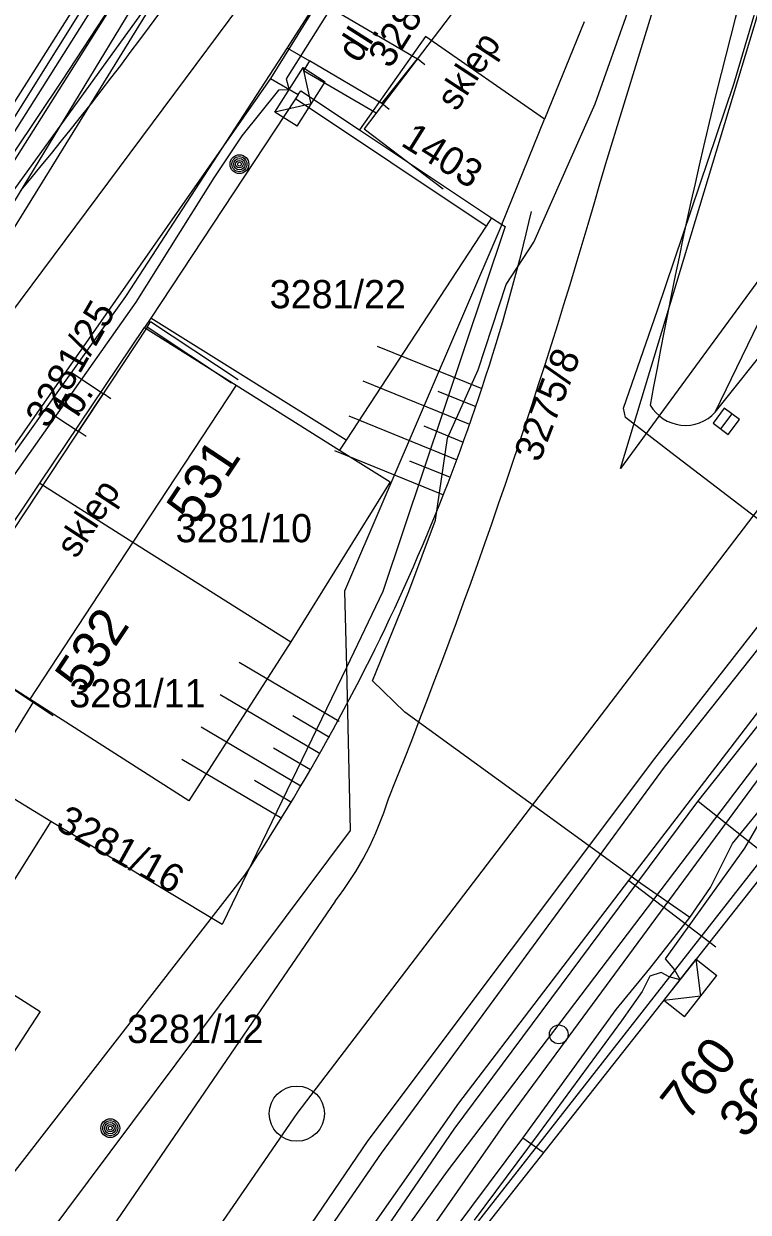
# Model space of a CAD drawing. Extents: x -601580 to 4, y -1204314 to 4.
# Drawn here: x -599644.63 to -599625.36, y -1204061.88 to -1204030.29 of the extents above; entities that cross this region are included whole.
import ezdxf

# ---------------------------------------------------------------- set-up
doc = ezdxf.new("R2010")
doc.units = 0
for name, color, linetype in [('00-EON NN', 7, 'Continuous'), ('00-INNOGY-NTL', 7, 'Continuous'), ('00-KN-HRANICE PARCEL', 7, 'Continuous'), ('00-KN-PARC. CISLA', 7, 'Continuous'), ('00-KN-VNITRNI KRESBA', 7, 'Continuous'), ('00-POLOHOPIS', 7, 'Continuous'), ('00-SITE KOM. KABEL', 7, 'Continuous'), ('00-VAK-KANAL-POTRUBI', 7, 'Continuous'), ('00-VAK-VODA-RAD IGIS', 7, 'Continuous'), ('Vrstva 25', 7, 'Continuous'), ('Vrstva 27', 7, 'Continuous'), ('Vrstva 28', 7, 'Continuous'), ('Vrstva 6', 7, 'Continuous'), ('Vrstva 9', 7, 'Continuous')]:
    doc.layers.add(name, color=color, linetype=linetype)

# ---------------------------------------------------------------- blocks, each defined once
blk = doc.blocks.new('6.01A_958')
at = {"layer": 'Vrstva 25'}
for radius in [0.25, 0.2, 0.15, 0.1, 0.05]:
    blk.add_circle((0, 0), radius, dxfattribs=at)
blk = doc.blocks.new('6.01A_960')
at = {"layer": 'Vrstva 25'}
for radius in [0.25, 0.2, 0.15, 0.1, 0.05]:
    blk.add_circle((0, 0), radius, dxfattribs=at)
blk = doc.blocks.new('6.14A_116')
at = {"layer": 'Vrstva 28'}
blk.add_circle((0, 0), 0.25, dxfattribs=at)
blk = doc.blocks.new('6.30_54')
at = {"layer": 'Vrstva 27'}
blk.add_line((-0.25, 0), (0.25, 0), dxfattribs=at)
blk.add_lwpolyline([(-0.25, -0.25), (0.25, -0.25), (0.25, 0.25), (-0.25, 0.25)], close=True, dxfattribs=at)
blk = doc.blocks.new('VCHOD_1550')
at = {"layer": 'Vrstva 6'}
blk.add_line((0, 0.251), (0, 0), dxfattribs=at)
blk = doc.blocks.new('VCHOD_1552')
at = {"layer": 'Vrstva 6'}
blk.add_line((0, 0.251), (0, 0), dxfattribs=at)
blk = doc.blocks.new('VCHOD_1554')
at = {"layer": 'Vrstva 6'}
blk.add_line((0, 0.25), (0, 0), dxfattribs=at)
blk = doc.blocks.new('VCHOD_1556')
at = {"layer": 'Vrstva 6'}
blk.add_line((0, 0.25), (0, 0), dxfattribs=at)
blk = doc.blocks.new('NN630')
at = {"layer": 'Vrstva 9'}
for points in [[(-3, -700), (-703, 0)], [(-703, -700), (-703, 0), (697, 0), (697, -700)], [(-3, -700), (697, 0)], [(-703, -700), (697, -700)]]:
    blk.add_lwpolyline(points, dxfattribs=at)

msp = doc.modelspace()

# ---------------------------------------------------------------- linework, layer by layer
at = {"layer": '00-EON NN'}
for points in [[(-599639.626, -1204025.602), (-599645.817, -1204035.392), (-599652.109, -1204039.668), (-599681.701, -1204079.546), (-599681.569, -1204080.026), (-599681.369, -1204080.316), (-599681.408, -1204080.723), (-599688.696, -1204090.4), (-599688.958, -1204090.416)], [(-599674.016, -1204068.519), (-599668.892, -1204061.614), (-599668.999, -1204061.544), (-599668.975, -1204061.303), (-599668.772, -1204061.218), (-599668.654, -1204061.293), (-599660.063, -1204049.715), (-599660.057, -1204049.47), (-599659.824, -1204049.394), (-599657.673, -1204046.495), (-599657.713, -1204046.217), (-599657.435, -1204046.173), (-599652.394, -1204039.38), (-599646.111, -1204035.109), (-599640.072, -1204025.558)], [(-599634.111, -1204026.139), (-599637.649, -1204031.756), (-599637.575, -1204032.05), (-599637.859, -1204032.056), (-599638.829, -1204033.276), (-599639.579, -1204034.386), (-599641.649, -1204037.696), (-599646.569, -1204044.656), (-599649.609, -1204049.086), (-599651.239, -1204051.216), (-599652.409, -1204052.916), (-599655.679, -1204058.396), (-599656.009, -1204058.936), (-599655.859, -1204059.306), (-599655.181, -1204060.036)], [(-599640.793, -1204072.36), (-599631.81, -1204059.488), (-599624.178, -1204049.131), (-599611.694, -1204033.201), (-599608.009, -1204028.683)], [(-599623.769, -1204049.286), (-599625.46, -1204052.206), (-599627.574, -1204055.15), (-599627.329, -1204055.44), (-599627.177, -1204055.706), (-599627.47, -1204055.627), (-599627.678, -1204055.511), (-599627.979, -1204055.606), (-599628.189, -1204056.016), (-599628.739, -1204056.796), (-599630.949, -1204059.806), (-599632.649, -1204062.096)]]:
    msp.add_lwpolyline(points, dxfattribs=at)
at = {"layer": '00-INNOGY-NTL'}
msp.add_line((-599628.54, -1204053.066), (-599626.23, -1204054.826), dxfattribs=at)
for points in [[(-599639.42, -1204068.056), (-599633.06, -1204058.986), (-599628.54, -1204053.066), (-599624.97, -1204048.416), (-599621.94, -1204048.086), (-599618.03, -1204043.316), (-599617.27, -1204042.386), (-599606.76, -1204029.536), (-599602.89, -1204024.726), (-599597.89, -1204018.516), (-599588.752, -1204007.679), (-599588.721, -1204007.642), (-599587.72, -1204006.456), (-599582.95, -1204001.026), (-599580.65, -1203998.396), (-599573.21, -1203990.296)], [(-599682.72, -1204081.816), (-599682.42, -1204081.416), (-599674.13, -1204070.426), (-599673.3, -1204069.306), (-599665.47, -1204058.716), (-599665.32, -1204058.516), (-599662.75, -1204055.006), (-599657.15, -1204047.396), (-599655.19, -1204044.816), (-599652.98, -1204041.906), (-599651.76, -1204040.706), (-599647.79, -1204037.416), (-599645.17, -1204035.496), (-599639.63, -1204026.376), (-599634.03, -1204017.786), (-599631.55, -1204013.466), (-599631.94, -1204011.566), (-599632.76, -1204007.646), (-599632.25, -1204006.826)]]:
    msp.add_lwpolyline(points, dxfattribs=at)
at = {"layer": '00-KN-HRANICE PARCEL'}
for p, q in [((-599629.729, -1204030.246), (-599630.779, -1204032.826)), ((-599638.069, -1204031.746), (-599649.409, -1204047.976)), ((-599638.069, -1204031.746), (-599637.329, -1204032.176)), ((-599631.919, -1204035.626), (-599630.779, -1204032.826)), ((-599635.699, -1204033.116), (-599632.189, -1204035.456)), ((-599632.189, -1204035.456), (-599631.919, -1204035.626)), ((-599644.199, -1204042.506), (-599641.419, -1204038.366)), ((-599646.979, -1204046.646), (-599644.199, -1204042.506)), ((-599643.909, -1204051.496), (-599645.679, -1204050.416)), ((-599643.909, -1204051.496), (-599646.259, -1204055.236)), ((-599625.029, -1204052.526), (-599632.569, -1204062.156))]:
    msp.add_line(p, q, dxfattribs=at)
for points in [[(-599624.459, -1204011.696), (-599625.399, -1204011.826), (-599626.079, -1204012.446), (-599638.069, -1204031.746)], [(-599614.819, -1204023.096), (-599628.759, -1204042.116), (-599622.319, -1204020.806)], [(-599651.609, -1204037.276), (-599650.659, -1204037.946), (-599646.529, -1204034.986), (-599643.369, -1204030.006)], [(-599630.779, -1204032.826), (-599633.949, -1204030.636), (-599635.699, -1204033.116)], [(-599637.329, -1204032.176), (-599637.259, -1204032.076), (-599635.699, -1204033.116)], [(-599637.329, -1204032.176), (-599637.399, -1204032.286), (-599641.249, -1204038.116), (-599641.419, -1204038.366)], [(-599632.189, -1204035.456), (-599632.329, -1204035.676), (-599636.059, -1204041.366), (-599636.229, -1204041.626)], [(-599631.919, -1204035.626), (-599636.099, -1204045.376), (-599636.049, -1204047.406)], [(-599631.919, -1204035.626), (-599631.829, -1204035.686), (-599635.079, -1204045.386), (-599636.049, -1204047.406)], [(-599641.419, -1204038.366), (-599638.979, -1204039.896), (-599636.229, -1204041.626)], [(-599636.229, -1204041.626), (-599634.889, -1204042.466), (-599637.529, -1204046.726)], [(-599644.199, -1204042.506), (-599641.729, -1204044.076), (-599637.529, -1204046.726)], [(-599644.369, -1204048.306), (-599644.469, -1204048.246), (-599646.979, -1204046.646)], [(-599637.529, -1204046.726), (-599640.239, -1204050.946), (-599644.369, -1204048.306)], [(-599636.049, -1204047.406), (-599635.949, -1204051.736), (-599644.069, -1204062.596), (-599673.189, -1204101.876)], [(-599636.049, -1204047.406), (-599639.349, -1204054.236), (-599643.909, -1204051.496)], [(-599644.369, -1204048.306), (-599645.579, -1204050.256), (-599645.679, -1204050.416)], [(-599646.259, -1204055.236), (-599644.189, -1204056.546), (-599646.779, -1204060.506)]]:
    msp.add_lwpolyline(points, dxfattribs=at)
at = {"layer": '00-KN-VNITRNI KRESBA'}
for p, q in [((-599632.329, -1204035.676), (-599637.399, -1204032.286)), ((-599636.059, -1204041.366), (-599641.249, -1204038.116)), ((-599638.979, -1204039.896), (-599641.729, -1204044.076)), ((-599641.729, -1204044.076), (-599644.469, -1204048.246))]:
    msp.add_line(p, q, dxfattribs=at)
at = {"layer": '00-POLOHOPIS'}
for p, q in [((-599629.154, -1204034.01), (-599623.197, -1204014.673)), ((-599637.616, -1204030.936), (-599630.716, -1204020.105)), ((-599636.811, -1204029.673), (-599634.162, -1204031.228)), ((-599626.702, -1204050.965), (-599610.461, -1204030.438)), ((-599626.241, -1204040.622), (-599618.069, -1204030.352)), ((-599641.916, -1204037.545), (-599637.616, -1204030.936)), ((-599637.618, -1204030.94), (-599637.035, -1204031.282)), ((-599637.035, -1204031.282), (-599637.187, -1204031.541)), ((-599635.108, -1204032.415), (-599637.035, -1204031.282)), ((-599635.108, -1204032.415), (-599634.162, -1204031.228)), ((-599635.26, -1204032.674), (-599637.187, -1204031.541)), ((-599626.241, -1204040.622), (-599623.701, -1204035.35)), ((-599649.42, -1204048.052), (-599641.916, -1204037.545)), ((-599641.349, -1204038.36), (-599641.255, -1204038.218)), ((-599638.929, -1204039.759), (-599641.255, -1204038.218)), ((-599635.233, -1204038.86), (-599632.45, -1204039.993)), ((-599643.36, -1204039.567), (-599642.518, -1204040.124)), ((-599635.61, -1204039.786), (-599632.773, -1204040.941)), ((-599642.518, -1204040.124), (-599643.18, -1204041.125)), ((-599633.617, -1204040.058), (-599632.609, -1204040.468)), ((-599644.058, -1204040.544), (-599643.18, -1204041.125)), ((-599635.987, -1204040.712), (-599633.114, -1204041.882)), ((-599633.994, -1204040.984), (-599632.941, -1204041.412)), ((-599636.364, -1204041.639), (-599633.472, -1204042.816)), ((-599634.371, -1204041.91), (-599633.291, -1204042.35)), ((-599638.9, -1204047.261), (-599636.243, -1204048.828)), ((-599639.408, -1204048.122), (-599636.751, -1204049.689)), ((-599637.476, -1204048.681), (-599636.497, -1204049.258)), ((-599639.916, -1204048.984), (-599637.259, -1204050.551)), ((-599637.984, -1204049.543), (-599637.005, -1204050.12)), ((-599640.424, -1204049.845), (-599637.767, -1204051.412)), ((-599638.491, -1204050.404), (-599637.513, -1204050.981)), ((-599633.181, -1204059.674), (-599626.702, -1204050.965)), ((-599626.697, -1204050.959), (-599624.688, -1204052.549)), ((-599645.189, -1204061.212), (-599638.752, -1204052.929)), ((-599636.348, -1204053.617), (-599645.944, -1204067.619)), ((-599641.682, -1204072.091), (-599633.181, -1204059.674))]:
    msp.add_line(p, q, dxfattribs=at)
for points in [[(-599642.827, -1204020.049), (-599638.621, -1204022.753), (-599646.303, -1204035.038), (-599652.026, -1204031.448)], [(-599630.013, -1204029.396), (-599631.882, -1204028.227), (-599635.575, -1204033.088), (-599633.476, -1204034.682)], [(-599639.109, -1204039.844), (-599641.349, -1204038.36), (-599646.863, -1204046.686), (-599643.849, -1204048.682)], [(-599628.107, -1204064.924), (-599632.312, -1204062.219), (-599624.688, -1204052.549), (-599620.802, -1204055.623)]]:
    msp.add_lwpolyline(points, dxfattribs=at)
for centre, radius, start, end in [((-599494.15, -1204064.427), 135.954, 156.32568, 169.83375), ((-599708.413, -1203981.082), 83.281, 319.90246, 338.6064), ((-599792.072, -1203987.719), 169.367, 338.09665, 344.13821), ((-599683.641, -1204023.056), 53.92, 326.3573, 346.8909), ((-599627.035, -1204039.889), 1.08, 210.1061, 317.279), ((-599643.106, -1204048.364), 8.559, 322.1447, 342.7684)]:
    msp.add_arc(centre, radius, start, end, dxfattribs=at)
at = {"layer": '00-SITE KOM. KABEL'}
for points in [[(-599621.999, -1204045.836), (-599627.419, -1204041.686), (-599628.629, -1204040.756), (-599628.679, -1204040.516), (-599627.779, -1204037.906), (-599625.749, -1204031.896), (-599624.359, -1204027.186), (-599621.759, -1204018.006), (-599620.119, -1204013.106), (-599616.529, -1204007.296), (-599616.179, -1204006.226), (-599625.499, -1203998.926)], [(-599634.399, -1204017.386), (-599636.549, -1204020.736), (-599637.419, -1204022.216), (-599639.569, -1204025.626), (-599643.609, -1204031.796), (-599646.209, -1204035.656), (-599649.869, -1204038.616), (-599652.939, -1204040.806), (-599654.929, -1204043.566), (-599656.079, -1204045.216), (-599657.779, -1204047.476)], [(-599626.919, -1204054.046), (-599628.219, -1204053.146), (-599634.499, -1204048.596), (-599635.359, -1204047.756), (-599634.389, -1204045.386), (-599633.679, -1204043.486), (-599633.359, -1204041.306), (-599632.549, -1204039.496), (-599631.799, -1204037.226), (-599631.069, -1204036.096), (-599630.109, -1204033.936), (-599629.439, -1204032.426), (-599628.519, -1204029.856), (-599626.749, -1204025.566), (-599625.819, -1204024.306)], [(-599626.919, -1204054.046), (-599626.369, -1204053.256), (-599625.779, -1204052.086), (-599623.279, -1204049.016), (-599620.429, -1204045.536)], [(-599706.729, -1204171.726), (-599707.939, -1204170.796), (-599690.829, -1204145.256), (-599680.939, -1204130.676), (-599669.219, -1204113.236), (-599666.739, -1204109.486), (-599666.509, -1204107.356), (-599660.459, -1204098.156), (-599658.139, -1204095.976), (-599651.239, -1204085.636), (-599633.359, -1204060.796), (-599621.999, -1204045.836)], [(-599628.219, -1204053.146), (-599634.499, -1204048.596)], [(-599625.779, -1204052.086), (-599623.279, -1204049.016)], [(-599631.359, -1204059.916), (-599628.879, -1204056.496), (-599627.979, -1204055.406), (-599626.919, -1204054.046)], [(-599628.879, -1204056.496), (-599627.979, -1204055.406)], [(-599631.359, -1204059.916), (-599628.879, -1204056.496)], [(-599635.429, -1204065.366), (-599631.359, -1204059.916)], [(-599630.819, -1204060.296), (-599631.359, -1204059.916)]]:
    msp.add_lwpolyline(points, dxfattribs=at)
at = {"layer": '00-VAK-KANAL-POTRUBI'}
for points in [[(-599626.8, -1204005.402), (-599630.251, -1204012.03), (-599631.791, -1204014.521), (-599636.291, -1204021.796), (-599646.199, -1204037.815), (-599650.415, -1204043.708)], [(-599616.896, -1204032.451), (-599637.368, -1204059.264)], [(-599637.368, -1204059.264), (-599663.469, -1204097.156)]]:
    msp.add_lwpolyline(points, dxfattribs=at)
msp.add_circle((-599637.368, -1204059.264), 0.735, dxfattribs=at)
at = {"layer": '00-VAK-VODA-RAD IGIS'}
for points in [[(-599623.788, -1204001.568), (-599633.812, -1204019.37), (-599644.963, -1204034.808), (-599652.205, -1204044.164), (-599669.243, -1204066.594), (-599684.387, -1204086.47)], [(-599681.29, -1204085.896), (-599664.657, -1204064.072), (-599655.799, -1204052.518), (-599626.628, -1204013.348), (-599623.659, -1204008.971)], [(-599613.689, -1204031.696), (-599627.859, -1204049.826), (-599635.479, -1204059.976), (-599650.069, -1204081.406), (-599663.221, -1204099.95)], [(-599613.729, -1204032.576), (-599627.599, -1204050.056), (-599635.129, -1204060.316), (-599649.649, -1204081.406), (-599663.669, -1204101.526)]]:
    msp.add_lwpolyline(points, dxfattribs=at)

# ---------------------------------------------------------------- block references
at = {"layer": '00-EON NN', "xscale": 0.001}
for p, yscale, rotation in [((-599637.575, -1204032.049), 0.001, 57.60144165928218), ((-599627.177, -1204055.705), 0.0010000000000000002, 51.74712504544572)]:
    msp.add_blockref('NN630', p, dxfattribs=dict(at, yscale=yscale, rotation=rotation))
at = {"layer": '00-POLOHOPIS'}
for name, p, xscale, yscale, rotation in [('VCHOD_1550', (-599634.162, -1204031.228), 0.99999871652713, 0.9999987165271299, -128.55367992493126), ('VCHOD_1552', (-599635.108, -1204032.415), 0.99999871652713, 0.9999987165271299, -128.55367992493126), ('VCHOD_1554', (-599642.518, -1204040.124), 0.9999978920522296, 0.9999978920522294, -123.47820942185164), ('6.30_54', (-599625.951, -1204040.86), 1.00000099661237, 1.00000099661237, -126.89060167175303), ('VCHOD_1556', (-599643.18, -1204041.125), 0.9999978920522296, 0.9999978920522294, -123.47820942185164)]:
    msp.add_blockref(name, p, dxfattribs=dict(at, xscale=xscale, yscale=yscale, rotation=rotation))
at = {"layer": '00-POLOHOPIS', "rotation": -90.00000000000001}
for name, p in [('6.01A_960', (-599638.895, -1204034.026)), ('6.14A_116', (-599630.403, -1204057.157)), ('6.01A_958', (-599642.328, -1204059.65))]:
    msp.add_blockref(name, p, dxfattribs=at)

# ---------------------------------------------------------------- texts
at = {"layer": '00-KN-PARC. CISLA'}
for s, rotation, p in [('3281/17', 58, (-599634.885, -1204031.515)), ('1403', 328, (-599634.633, -1204033.514)), ('3281/25', 60, (-599643.982, -1204041.081)), ('3275/8', 69, (-599630.915, -1204041.98)), ('3281/16', 331, (-599643.817, -1204051.682))]:
    msp.add_text(s, height=0.75, rotation=rotation, dxfattribs=at).set_placement(p)
for s, p in [('3281/22', (-599638.091, -1204037.856)), ('3281/10', (-599640.589, -1204044.076)), ('3281/11', (-599643.419, -1204048.465)), ('3281/12', (-599641.879, -1204057.386))]:
    msp.add_text(s, height=0.75, dxfattribs=at).set_placement(p)
at = {"layer": '00-POLOHOPIS'}
for s, height, rotation, p in [('dl.', 0.75, 57.5288, (-599635.72, -1204031.369)), ('sklep', 0.7, 56.7548, (-599633.118, -1204032.645)), ('b.', 0.75, 56.4715, (-599643.202, -1204040.783)), ('531', 1, 56.485, (-599640.062, -1204043.661)), ('sklep', 0.7, 56.7548, (-599643.235, -1204044.535)), ('532', 1, 56.485, (-599643.026, -1204048.136)), ('760', 1, 51.7471, (-599626.987, -1204059.502)), ('36', 1, 51.7471, (-599625.439, -1204059.961))]:
    msp.add_text(s, height=height, rotation=rotation, dxfattribs=at).set_placement(p)

doc.saveas('drawing.dxf')
